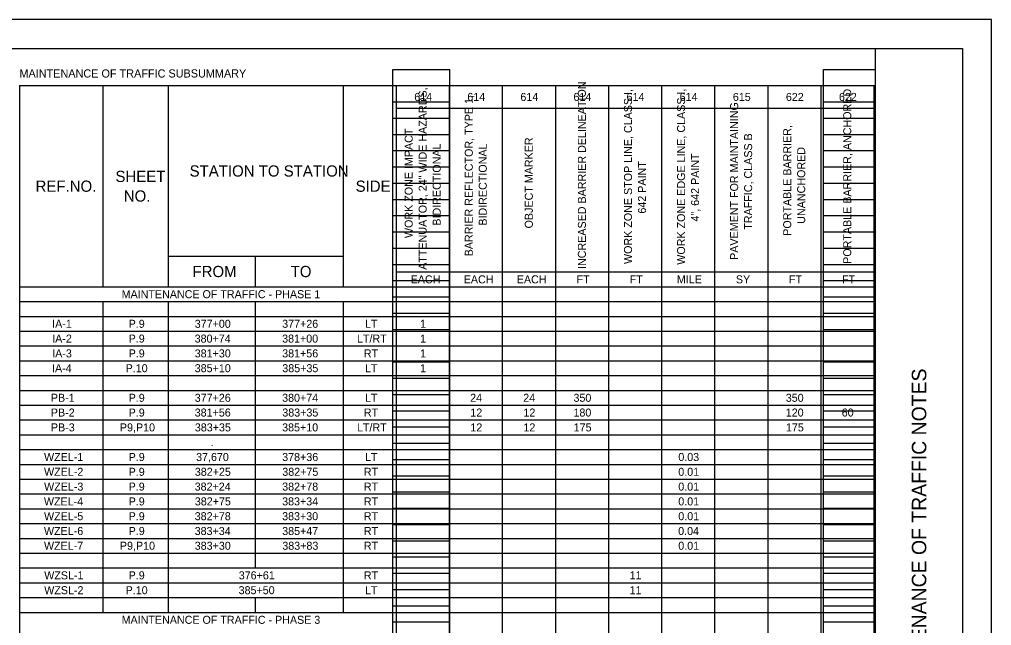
# Model space of a CAD drawing. Extents: x -18.6 to 34, y -8.1 to 37.1.
# Drawn here: x 17.24 to 34, y 11.56 to 22 of the extents above; entities that cross this region are included whole.
import ezdxf

# ---------------------------------------------------------------- set-up
doc = ezdxf.new("R2010")
doc.units = 0
for name, color, linetype in [('Default', 7, 'Continuous'), ('SH_Border', 7, 'Continuous'), ('SH_Cut_Line', 7, 'Continuous'), ('SH_Data', 7, 'Continuous'), ('SH_Text', 7, 'Continuous')]:
    doc.layers.add(name, color=color, linetype=linetype)

msp = doc.modelspace()

# ---------------------------------------------------------------- linework, layer by layer
at = {"layer": 'SH_Border'}
msp.add_line((32, 0.5), (32, 21.5), dxfattribs=at)
msp.add_lwpolyline([(1.5, 21.5), (33.5, 21.5), (33.5, 0.5), (1.5, 0.5)], close=True, dxfattribs=at)
at = {"layer": 'SH_Cut_Line'}
msp.add_lwpolyline([(0, 0), (34, 0), (34, 22), (0, 22)], close=True, dxfattribs=at)
at = {"layer": 'SH_Data'}
for p, q in [((23.68, 0.98), (23.68, 21.14)), ((23.68, 21.14), (24.66, 21.14)), ((24.66, 0.98), (24.66, 21.14)), ((31.1, 0.98), (31.1, 21.14)), ((31.1, 21.14), (32, 21.14)), ((32, 0.98), (32, 21.14)), ((23.68, 20.86), (24.66, 20.86)), ((31.1, 20.86), (32, 20.86)), ((23.68, 20.58), (24.66, 20.58)), ((31.1, 20.58), (32, 20.58)), ((23.68, 20.3), (24.66, 20.3)), ((31.1, 20.3), (32, 20.3)), ((23.68, 20.02), (24.66, 20.02)), ((31.1, 20.02), (32, 20.02)), ((23.68, 19.74), (24.66, 19.74)), ((31.1, 19.74), (32, 19.74)), ((23.68, 19.46), (24.66, 19.46)), ((31.1, 19.46), (32, 19.46)), ((23.68, 19.18), (24.66, 19.18)), ((31.1, 19.18), (32, 19.18)), ((23.68, 18.9), (24.66, 18.9)), ((31.1, 18.9), (32, 18.9)), ((23.68, 18.62), (24.66, 18.62)), ((31.1, 18.62), (32, 18.62)), ((23.68, 18.34), (24.66, 18.34)), ((31.1, 18.34), (32, 18.34)), ((23.68, 18.06), (24.66, 18.06)), ((31.1, 18.06), (32, 18.06)), ((23.68, 17.78), (24.66, 17.78)), ((31.1, 17.78), (32, 17.78)), ((23.68, 17.5), (24.66, 17.5)), ((31.1, 17.5), (32, 17.5)), ((23.68, 17.22), (24.66, 17.22)), ((31.1, 17.22), (32, 17.22)), ((23.68, 16.94), (24.66, 16.94)), ((31.1, 16.94), (32, 16.94)), ((23.68, 16.66), (24.66, 16.66)), ((31.1, 16.66), (32, 16.66)), ((23.68, 16.38), (24.66, 16.38)), ((31.1, 16.38), (32, 16.38)), ((23.68, 16.1), (24.66, 16.1)), ((31.1, 16.1), (32, 16.1)), ((23.68, 15.82), (24.66, 15.82)), ((31.1, 15.82), (32, 15.82)), ((23.68, 15.54), (24.66, 15.54)), ((31.1, 15.54), (32, 15.54)), ((23.68, 15.26), (24.66, 15.26)), ((31.1, 15.26), (32, 15.26)), ((23.68, 14.98), (24.66, 14.98)), ((31.1, 14.98), (32, 14.98)), ((23.68, 14.7), (24.66, 14.7)), ((31.1, 14.7), (32, 14.7)), ((23.68, 14.42), (24.66, 14.42)), ((31.1, 14.42), (32, 14.42)), ((23.68, 14.14), (24.66, 14.14)), ((31.1, 14.14), (32, 14.14)), ((23.68, 13.86), (24.66, 13.86)), ((31.1, 13.86), (32, 13.86)), ((23.68, 13.58), (24.66, 13.58)), ((31.1, 13.58), (32, 13.58)), ((23.68, 13.3), (24.66, 13.3)), ((31.1, 13.3), (32, 13.3)), ((23.68, 13.02), (24.66, 13.02)), ((31.1, 13.02), (32, 13.02)), ((23.68, 12.74), (24.66, 12.74)), ((31.1, 12.74), (32, 12.74)), ((23.68, 12.46), (24.66, 12.46)), ((31.1, 12.46), (32, 12.46)), ((23.68, 12.18), (24.66, 12.18)), ((31.1, 12.18), (32, 12.18)), ((23.68, 11.9), (24.66, 11.9)), ((31.1, 11.9), (32, 11.9)), ((23.68, 11.62), (24.66, 11.62)), ((31.1, 11.62), (32, 11.62))]:
    msp.add_line(p, q, dxfattribs=at)
at = {"layer": 'SH_Text'}
for p, q in [((17.24, 20.86), (31.97, 20.86)), ((17.24, 20.86), (17.24, 5.44)), ((18.68, 20.86), (18.68, 17.395)), ((19.805, 20.86), (19.805, 17.395)), ((22.82, 20.86), (22.82, 17.395)), ((23.735, 20.86), (23.735, 5.44)), ((24.65, 20.86), (24.65, 5.44)), ((25.565, 20.86), (25.565, 5.44)), ((26.48, 20.86), (26.48, 5.44)), ((27.395, 20.86), (27.395, 5.44)), ((28.31, 20.86), (28.31, 5.44)), ((29.225, 20.86), (29.225, 5.44)), ((30.14, 20.86), (30.14, 5.44)), ((31.055, 20.86), (31.055, 5.44)), ((31.97, 20.86), (31.97, 5.44)), ((23.735, 20.47), (31.97, 20.47)), ((19.805, 17.92), (22.82, 17.92)), ((21.305, 17.92), (21.305, 17.395)), ((23.735, 17.65), (31.97, 17.65)), ((17.24, 17.395), (31.97, 17.395)), ((17.24, 17.14), (23.735, 17.14)), ((18.68, 17.14), (18.68, 11.785)), ((19.805, 17.14), (19.805, 11.785)), ((21.305, 17.14), (21.305, 12.55)), ((22.82, 17.14), (22.82, 11.785)), ((23.735, 17.14), (31.97, 17.14)), ((17.24, 16.885), (31.97, 16.885)), ((17.24, 16.63), (31.97, 16.63)), ((17.24, 16.375), (31.97, 16.375)), ((17.24, 16.12), (31.97, 16.12)), ((17.24, 15.865), (31.97, 15.865)), ((17.24, 15.61), (31.97, 15.61)), ((17.24, 15.355), (31.97, 15.355)), ((17.24, 15.1), (31.97, 15.1)), ((17.24, 14.845), (31.97, 14.845)), ((17.24, 14.59), (31.97, 14.59)), ((17.24, 14.335), (31.97, 14.335)), ((17.24, 14.08), (31.97, 14.08)), ((17.24, 13.825), (31.97, 13.825)), ((17.24, 13.57), (31.97, 13.57)), ((17.24, 13.315), (31.97, 13.315)), ((17.24, 13.06), (31.97, 13.06)), ((17.24, 12.805), (31.97, 12.805)), ((17.24, 12.55), (31.97, 12.55)), ((17.24, 12.295), (31.97, 12.295)), ((17.24, 12.04), (31.97, 12.04)), ((21.305, 12.04), (21.305, 11.785)), ((17.24, 11.785), (23.735, 11.785)), ((23.735, 11.785), (31.97, 11.785))]:
    msp.add_line(p, q, dxfattribs=at)

# ---------------------------------------------------------------- texts
at = {"layer": 'Default'}
msp.add_text('MAINTENANCE OF TRAFFIC SUBSUMMARY', height=0.14, dxfattribs=at).set_placement((17.24, 21))
at = {"layer": 'SH_Data'}
msp.add_text('MAINTENANCE OF TRAFFIC NOTES', height=0.25, rotation=90, dxfattribs=at).set_placement((32.875, 10.247))
at = {"layer": 'SH_Text'}
for s, p in [('ATTENUATOR, 24" WIDE HAZARDS, ', (24.261, 17.687)), ('INCREASED BARRIER DELINEATION', (27.006, 17.701)), ('WORK ZONE STOP LINE, CLASS I, ', (27.801, 17.787)), ('WORK ZONE EDGE LINE, CLASS I, ', (28.716, 17.774)), ('PORTABLE BARRIER, ANCHORED', (31.581, 17.79)), ('BARRIER REFLECTOR, TYPE 1, ', (25.056, 17.919)), ('PAVEMENT FOR MAINTAINING ', (29.631, 17.858)), ('WORK ZONE IMPACT ', (24.02, 18.234)), ('PORTABLE BARRIER, ', (30.546, 18.273)), ('OBJECT MARKER', (26.091, 18.4)), ('TRAFFIC, CLASS B', (29.872, 18.378)), ('BIDIRECTIONAL', (24.503, 18.448)), ('BIDIRECTIONAL', (25.297, 18.448)), ('UNANCHORED', (30.787, 18.48)), ('4", 642 PAINT', (28.957, 18.519)), ('642 PAINT', (28.042, 18.655))]:
    msp.add_text(s, height=0.138, rotation=90, dxfattribs=at).set_placement(p)
for s, height, p in [('614', 0.138, (24.047, 20.596)), ('614', 0.138, (24.962, 20.596)), ('614', 0.138, (25.877, 20.596)), ('614', 0.138, (26.792, 20.596)), ('614', 0.138, (27.707, 20.596)), ('614', 0.138, (28.622, 20.596)), ('615', 0.138, (29.54, 20.596)), ('622', 0.138, (30.454, 20.596)), ('622', 0.138, (31.369, 20.596)), ('STATION TO STATION', 0.1932, (20.174, 19.293)), ('SHEET ', 0.1932, (18.895, 19.2)), ('REF.NO.', 0.1932, (17.518, 19.031)), ('SIDE', 0.1932, (23.036, 19.031)), ('NO.', 0.1932, (19.039, 18.862)), ('FROM', 0.1932, (20.223, 17.561)), ('TO', 0.1932, (21.916, 17.561)), ('EACH', 0.138, (23.985, 17.453)), ('EACH', 0.138, (24.9, 17.453)), ('EACH', 0.138, (25.815, 17.453)), ('FT', 0.138, (26.846, 17.453)), ('FT', 0.138, (27.761, 17.453)), ('MILE', 0.138, (28.575, 17.453)), ('SY', 0.138, (29.592, 17.453)), ('FT', 0.138, (30.506, 17.453)), ('FT', 0.138, (31.421, 17.453)), ('MAINTENANCE OF TRAFFIC - PHASE 1', 0.138, (19.002, 17.198)), ('IA-1', 0.138, (17.804, 16.688)), ('P.9', 0.138, (19.123, 16.688)), ('377+00', 0.138, (20.262, 16.688)), ('377+26', 0.138, (21.77, 16.688)), ('LT', 0.138, (23.197, 16.688)), ('1', 0.138, (24.148, 16.688)), ('IA-2', 0.138, (17.805, 16.433)), ('P.9', 0.138, (19.123, 16.433)), ('380+74', 0.138, (20.261, 16.433)), ('381+00', 0.138, (21.769, 16.433)), ('LT/RT', 0.138, (23.059, 16.433)), ('1', 0.138, (24.148, 16.433)), ('IA-3', 0.138, (17.805, 16.178)), ('P.9', 0.138, (19.123, 16.178)), ('381+30', 0.138, (20.262, 16.178)), ('381+56', 0.138, (21.77, 16.178)), ('RT', 0.138, (23.178, 16.178)), ('1', 0.138, (24.148, 16.178)), ('IA-4', 0.138, (17.802, 15.923)), ('P.10', 0.138, (19.071, 15.923)), ('385+10', 0.138, (20.262, 15.923)), ('385+35', 0.138, (21.772, 15.923)), ('LT', 0.138, (23.197, 15.923)), ('1', 0.138, (24.148, 15.923)), ('PB-1', 0.138, (17.782, 15.413)), ('P.9', 0.138, (19.123, 15.413)), ('377+26', 0.138, (20.262, 15.413)), ('380+74', 0.138, (21.769, 15.413)), ('LT', 0.138, (23.197, 15.413)), ('24', 0.138, (25.011, 15.413)), ('24', 0.138, (25.926, 15.413)), ('350', 0.138, (26.792, 15.413)), ('350', 0.138, (30.452, 15.413)), ('PB-2', 0.138, (17.782, 15.159)), ('P.9', 0.138, (19.123, 15.159)), ('381+56', 0.138, (20.262, 15.159)), ('383+35', 0.138, (21.772, 15.159)), ('RT', 0.138, (23.178, 15.159)), ('12', 0.138, (25.014, 15.159)), ('12', 0.138, (25.929, 15.159)), ('180', 0.138, (26.792, 15.159)), ('120', 0.138, (30.452, 15.159)), ('60', 0.138, (31.417, 15.159)), ('PB-3', 0.138, (17.783, 14.903)), ('P9,P10', 0.138, (18.972, 14.903)), ('383+35', 0.138, (20.264, 14.903)), ('385+10', 0.138, (21.769, 14.903)), ('LT/RT', 0.138, (23.059, 14.903)), ('12', 0.138, (25.014, 14.903)), ('12', 0.138, (25.929, 14.903)), ('175', 0.138, (26.795, 14.903)), ('175', 0.138, (30.455, 14.903)), ('.', 0.138, (20.538, 14.649)), ('WZEL-1', 0.138, (17.664, 14.393)), ('P.9', 0.138, (19.123, 14.393)), ('37,670', 0.138, (20.286, 14.393)), ('378+36', 0.138, (21.77, 14.393)), ('LT', 0.138, (23.197, 14.393)), ('0.03', 0.138, (28.6, 14.393)), ('WZEL-2', 0.138, (17.664, 14.138)), ('P.9', 0.138, (19.123, 14.138)), ('382+25', 0.138, (20.264, 14.138)), ('382+75', 0.138, (21.772, 14.138)), ('RT', 0.138, (23.178, 14.138)), ('0.01', 0.138, (28.599, 14.138)), ('WZEL-3', 0.138, (17.665, 13.883)), ('P.9', 0.138, (19.123, 13.883)), ('382+24', 0.138, (20.261, 13.883)), ('382+78', 0.138, (21.77, 13.883)), ('RT', 0.138, (23.178, 13.883)), ('0.01', 0.138, (28.599, 13.883)), ('WZEL-4', 0.138, (17.662, 13.628)), ('P.9', 0.138, (19.123, 13.628)), ('382+75', 0.138, (20.264, 13.628)), ('383+34', 0.138, (21.769, 13.628)), ('RT', 0.138, (23.178, 13.628)), ('0.01', 0.138, (28.599, 13.628)), ('WZEL-5', 0.138, (17.664, 13.373)), ('P.9', 0.138, (19.123, 13.373)), ('382+78', 0.138, (20.262, 13.373)), ('383+30', 0.138, (21.769, 13.373)), ('RT', 0.138, (23.178, 13.373)), ('0.01', 0.138, (28.599, 13.373)), ('WZEL-6', 0.138, (17.663, 13.118)), ('P.9', 0.138, (19.123, 13.118)), ('383+34', 0.138, (20.261, 13.118)), ('385+47', 0.138, (21.77, 13.118)), ('RT', 0.138, (23.178, 13.118)), ('0.04', 0.138, (28.597, 13.118)), ('WZEL-7', 0.138, (17.663, 12.864)), ('P9,P10', 0.138, (18.972, 12.864)), ('383+30', 0.138, (20.262, 12.864)), ('383+83', 0.138, (21.772, 12.864)), ('RT', 0.138, (23.178, 12.864)), ('0.01', 0.138, (28.599, 12.864)), ('WZSL-1', 0.138, (17.667, 12.354)), ('P.9', 0.138, (19.123, 12.354)), ('376+61', 0.138, (21.021, 12.354)), ('RT', 0.138, (23.178, 12.354)), ('11', 0.138, (27.759, 12.354)), ('WZSL-2', 0.138, (17.667, 12.098)), ('P.10', 0.138, (19.071, 12.098)), ('385+50', 0.138, (21.019, 12.098)), ('LT', 0.138, (23.197, 12.098)), ('11', 0.138, (27.759, 12.098)), ('MAINTENANCE OF TRAFFIC - PHASE 3', 0.138, (19.002, 11.588))]:
    msp.add_text(s, height=height, dxfattribs=at).set_placement(p)

doc.saveas('drawing.dxf')
